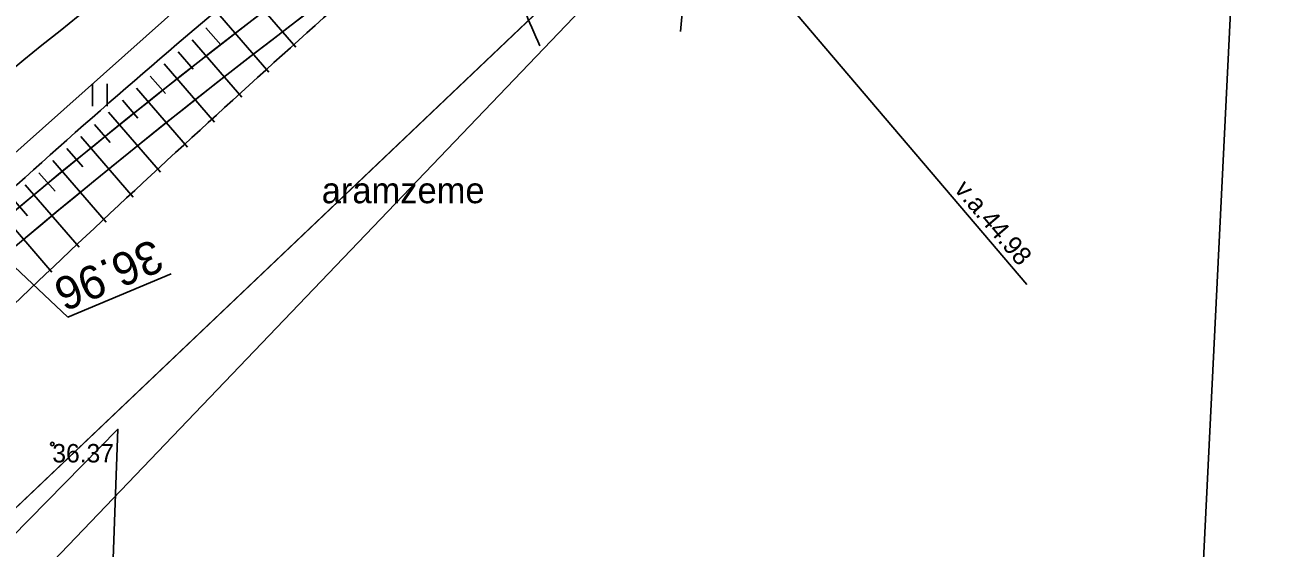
# Model space of a CAD drawing. Extents: x 469981 to 472086, y 246785 to 247785.
# Drawn here: x 470354.77 to 470388.62, y 247066.25 to 247080.43 of the extents above; entities that cross this region are included whole.
import ezdxf

# ---------------------------------------------------------------- set-up
doc = ezdxf.new("R2010")
doc.units = 0
for name, color, linetype in [('0_922', 7, 'Continuous'), ('0_Asfalta_mala', 7, 'Continuous'), ('0_Asfalta_Nomale', 7, 'Continuous'), ('0_Ruut_Braukt', 7, 'Continuous'), ('0_Ruut_nomale', 7, 'Continuous'), ('0_vertikals', 7, 'Continuous'), ('0_vertkals_cipari', 7, 'Continuous'), ('21', 7, 'Continuous'), ('CELI_CMAL_####_####_#', 7, 'Continuous'), ('DREN_VADP_####_####_#', 7, 'Continuous'), ('DREN_VADP_KLKT_####_#', 7, 'Continuous'), ('ELEK_VADV_ZSPR_####_#', 7, 'Continuous'), ('ELEK_VADV_ZSPR_TKST_#', 7, 'Continuous'), ('HIDG_GRAV_####_####_#', 7, 'Continuous'), ('RAMI_UZMR_####_####_#', 7, 'Continuous'), ('RELJ_AATZ_####_TKST_#', 7, 'Continuous'), ('RELJ_ELEM_####_####_#', 7, 'Continuous'), ('RELJ_NOGA_####_####_#', 7, 'Continuous'), ('RELJ_NOGL_####_####_#', 7, 'Continuous'), ('ROBZ_IERR_####_####_#', 7, 'Continuous'), ('ROBZ_PROJ_####_####_#', 7, 'Continuous'), ('TERT_ELEM_####_####_#', 7, 'Continuous'), ('TERT_IZMT_####_TKST_#', 7, 'Continuous'), ('TERT_KONT_####_####_#', 7, 'Continuous')]:
    doc.layers.add(name, color=color, linetype=linetype)

msp = doc.modelspace()

# ---------------------------------------------------------------- linework, layer by layer
at = {"layer": '0_922'}
msp.add_arc((470487.184, 246916.514), 210, 113.13829, 135.11501, dxfattribs=at)
at = {"layer": '0_Asfalta_mala'}
for radius in [213, 207]:
    msp.add_arc((470487.184, 246916.514), radius, 113.13829, 135.11501, dxfattribs=at)
at = {"layer": '0_Asfalta_Nomale'}
for radius, start in [(206.25, 113.13829), (213.75, 120.08211)]:
    msp.add_arc((470487.184, 246916.514), radius, start, 135.11501, dxfattribs=at)
at = {"layer": '0_Ruut_Braukt'}
for radius in [213, 207]:
    msp.add_arc((470487.184, 246916.514), radius, 113.13829, 135.11501, dxfattribs=at)
at = {"layer": '0_Ruut_nomale'}
for radius, end in [(207, 130.0782), (206.25, 130.16049)]:
    msp.add_arc((470487.184, 246916.514), radius, 113.13829, end, dxfattribs=at)
at = {"layer": '0_vertikals'}
for p, q in [((470353.631, 247074.668), (470355.929, 247072.509)), ((470355.929, 247072.509), (470358.74, 247073.685))]:
    msp.add_line(p, q, dxfattribs=at)
at = {"layer": '21'}
msp.add_arc((470487.184, 246916.514), 210, 113.13829, 135.11501, dxfattribs=at)
at = {"layer": 'CELI_CMAL_####_####_#'}
msp.add_lwpolyline([(470440.723, 247107.99), (470440.084, 247118.844), (470439.302, 247119.794), (470438.459, 247120.205), (470437.434, 247120.771), (470435.683, 247121.111), (470417.849, 247114.314), (470398.184, 247106.061), (470376.912, 247095.329), (470368.488, 247089.418), (470350.85, 247073.72), (470334.429, 247056.212), (470317.045, 247039.09), (470299.359, 247021.199), (470279.758, 247002.025), (470265.741, 246988.964), (470242.76, 246971.543), (470223.686, 246958.587), (470209.766, 246949.279)], dxfattribs=at)
at = {"layer": 'DREN_VADP_####_####_#'}
msp.add_lwpolyline([(470386.032, 247051.246), (470388.222, 247095.652)], dxfattribs=at)
at = {"layer": 'DREN_VADP_KLKT_####_#'}
msp.add_lwpolyline([(470355.84, 247029.317), (470356.44, 247045.884), (470357.293, 247069.467), (470322.272, 247033.825), (470311.427, 247022.787), (470278.296, 246989.068), (470265.457, 246976.001), (470248.264, 246964.754), (470217.931, 246944.913)], dxfattribs=at)
at = {"layer": 'ELEK_VADV_ZSPR_####_#'}
msp.add_line((470360.738, 247098.313), (470381.961, 247073.394), dxfattribs=at)
at = {"layer": 'HIDG_GRAV_####_####_#'}
msp.add_lwpolyline([(470372.562, 247080.256), (470372.938, 247084.442), (470373.238, 247088.396), (470373.423, 247089.506), (470373.862, 247090.454), (470374.301, 247090.824), (470375.017, 247090.963), (470375.295, 247090.593), (470375.272, 247089.113), (470374.786, 247081.228)], dxfattribs=at)
at = {"layer": 'RAMI_UZMR_####_####_#'}
msp.add_lwpolyline([(470682.857, 247179.693), (470601.924, 247155.957), (470538.749, 247139.954), (470448.7, 247112.965), (470443.256, 247108.572), (470439.042, 247107.166), (470426.399, 247105.409), (470390.93, 247093.141), (470379.516, 247082.95), (470369.859, 247080.841), (470357.567, 247068.014), (470285.914, 246993.254), (470269.057, 246978.845), (470246.406, 246963.908), (470178.978, 246918.441), (470154.395, 246901.045), (470104.604, 246871.942), (470081.833, 246858.073)], dxfattribs=at)
at = {"layer": 'RELJ_ELEM_####_####_#'}
msp.add_circle((470355.512, 247069.067), 0.05, dxfattribs=at)
at = {"layer": 'RELJ_NOGA_####_####_#'}
for p, q in [((470360.815, 247081.338), (470362.125, 247079.828)), ((470360.06, 247080.683), (470361.389, 247079.15)), ((470359.682, 247080.355), (470360.084, 247079.892)), ((470359.304, 247080.028), (470360.653, 247078.473)), ((470358.927, 247079.7), (470359.334, 247079.23)), ((470358.549, 247079.372), (470359.917, 247077.795)), ((470358.171, 247079.045), (470358.585, 247078.568)), ((470357.794, 247078.717), (470359.181, 247077.117)), ((470357.416, 247078.389), (470357.835, 247077.906)), ((470357.038, 247078.062), (470358.445, 247076.44)), ((470356.283, 247077.406), (470357.709, 247075.762)), ((470356.661, 247077.734), (470357.086, 247077.244)), ((470355.905, 247077.079), (470356.336, 247076.582)), ((470355.528, 247076.751), (470356.974, 247075.084)), ((470355.15, 247076.423), (470355.587, 247075.92)), ((470354.772, 247076.096), (470356.238, 247074.407)), ((470354.395, 247075.768), (470354.837, 247075.258)), ((470354.017, 247075.44), (470355.502, 247073.729))]:
    msp.add_line(p, q, dxfattribs=at)
msp.add_spline([(470120.845, 246890.769), (470123.591, 246892.466), (470150.351, 246909.177), (470171.26, 246922.106), (470191.149, 246935.734), (470210.204, 246948.514), (470224.202, 246958.074), (470243.113, 246970.411), (470266.522, 246987.913), (470280.536, 247001.251), (470299.823, 247020.383), (470317.592, 247038.544), (470334.877, 247055.828), (470351.425, 247073.192), (470366.151, 247085.967)], degree=3, dxfattribs=at)
at = {"layer": 'RELJ_NOGL_####_####_#'}
msp.add_spline([(470122.047, 246889.925), (470124.645, 246891.606), (470151.263, 246908.028), (470171.623, 246921.498), (470191.873, 246934.822), (470224.882, 246957.282), (470243.432, 246969.856), (470267.182, 246986.981), (470282.015, 246999.84), (470300.677, 247018.663), (470318.825, 247036.845), (470336.227, 247054.122), (470352.943, 247071.373), (470367.141, 247084.447)], degree=3, dxfattribs=at)
at = {"layer": 'ROBZ_IERR_####_####_#'}
msp.add_lwpolyline([(470310.127, 246974.356), (470275.956, 246992.729), (470371.503, 247083.47), (470396.219, 247097.502), (470431.624, 247112.202), (470468.364, 247124.23), (470636.973, 247175.147), (470640.03, 247134.708)], dxfattribs=at)
at = {"layer": 'ROBZ_PROJ_####_####_#'}
msp.add_lwpolyline([(471398.351, 247372.094), (471346.741, 247338.478), (471133.176, 247205.05), (471108.425, 247194.786), (471087.339, 247189.709), (471023.306, 247181.157), (470962.604, 247185.245), (470905.63, 247205.857), (470878.75, 247214.454), (470852.344, 247217.039), (470815.743, 247215.147), (470778.583, 247209.26), (470718.669, 247194.633), (470636.973, 247175.147), (470468.364, 247124.23), (470431.624, 247112.202), (470396.219, 247097.502), (470371.503, 247083.47), (470275.956, 246992.729), (470152.342, 246907.761), (470066.737, 246851.23)], dxfattribs=at)
at = {"layer": 'TERT_ELEM_####_####_#'}
for p, q in [((470356.599, 247078.232), (470356.599, 247078.832)), ((470356.999, 247078.232), (470356.999, 247078.832))]:
    msp.add_line(p, q, dxfattribs=at)
at = {"layer": 'TERT_KONT_####_####_#'}
msp.add_spline([(470367.141, 247084.447), (470367.929, 247081.854), (470368.74, 247079.866)], degree=3, dxfattribs=at)

# ---------------------------------------------------------------- texts
at = {"layer": '0_vertkals_cipari'}
msp.add_text('36.96', height=0.9, rotation=202.7111, dxfattribs=at).set_placement((470358.263, 247074.641))
at = {"layer": 'ELEK_VADV_ZSPR_TKST_#'}
msp.add_text('v.a.44.98', height=0.5, rotation=310.4202, dxfattribs=at).set_placement((470379.973, 247075.96))
at = {"layer": 'RELJ_AATZ_####_TKST_#'}
msp.add_text('36.37', height=0.5, dxfattribs=at).set_placement((470355.512, 247068.567))
at = {"layer": 'TERT_IZMT_####_TKST_#'}
msp.add_text('aramzeme', height=0.7, dxfattribs=at).set_placement((470362.824, 247075.596))

doc.saveas('drawing.dxf')
